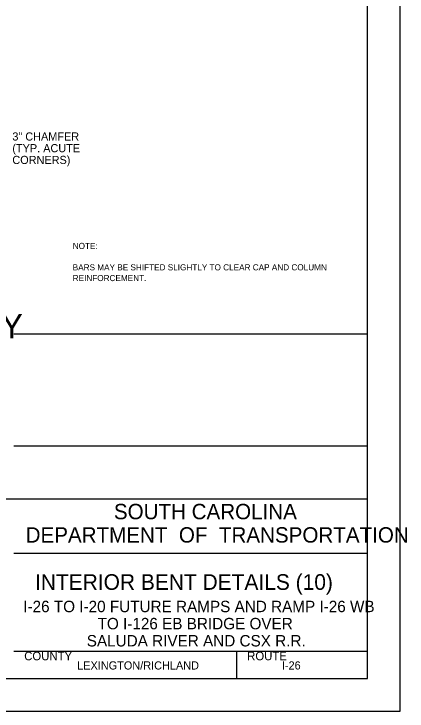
# Model space of a CAD drawing. Extents: x -146.3 to -98.2, y -113.4 to -84.1.
# Drawn here: x -106.2 to -98.17, y -113.39 to -99.15 of the extents above; entities that cross this region are included whole.
import ezdxf

# ---------------------------------------------------------------- set-up
doc = ezdxf.new("R2010")
doc.units = 0
for name, color, linetype in [('BR_AUTO DIMENSION', 7, 'Continuous'), ('BR_BORDER LINES', 7, 'Continuous'), ('BR_TEXT', 7, 'Continuous'), ('Level 31', 7, 'Continuous')]:
    doc.layers.add(name, color=color, linetype=linetype)

msp = doc.modelspace()

# ---------------------------------------------------------------- linework, layer by layer
at = {"layer": 'BR_BORDER LINES'}
for p, q in [((-98.979, -112.725), (-98.979, -84.726)), ((-106.201, -105.69), (-98.979, -105.69)), ((-106.201, -107.976), (-98.979, -107.976)), ((-108.979, -109.058), (-98.979, -109.058)), ((-106.201, -110.169), (-98.978, -110.169)), ((-106.201, -112.169), (-98.979, -112.169)), ((-106.071, -112.169), (-98.979, -112.169)), ((-101.645, -112.725), (-101.645, -112.169)), ((-143.866, -112.725), (-98.979, -112.725))]:
    msp.add_line(p, q, dxfattribs=at)
at = {"layer": 'Level 31'}
msp.add_line((-102.59, -110.756), (-102.59, -110.756), dxfattribs=at)
msp.add_lwpolyline([(-146.31, -113.391), (-98.311, -113.391), (-98.311, -84.059), (-146.31, -84.059)], close=True, dxfattribs=at)

# ---------------------------------------------------------------- texts
at = {"layer": 'BR_AUTO DIMENSION'}
for s, height, p in [('3" CHAMFER', 0.1662, (-106.233, -101.739)), ('(TYP. ACUTE', 0.16625, (-106.233, -101.978)), ('CORNERS)', 0.1662, (-106.233, -102.218)), ('NOTE:', 0.125, (-105, -103.954)), ('BARS MAY BE SHIFTED SLIGHTLY TO CLEAR CAP AND COLUMN', 0.125, (-105, -104.391)), ('REINFORCEMENT.', 0.125, (-105, -104.61))]:
    msp.add_text(s, height=height, dxfattribs=at).set_placement(p)
at = {"layer": 'BR_TEXT'}
msp.add_text('PLAN OF SHEAR KEY', height=0.50006, rotation=0, dxfattribs=at).set_placement((-112.893, -105.782))
for s, height, p in [('SOUTH CAROLINA', 0.31449, (-104.159, -109.474)), ('DEPARTMENT  OF  TRANSPORTATION', 0.31449, (-105.962, -109.951)), ('INTERIOR BENT DETAILS (10)', 0.31999, (-105.771, -110.916)), ('I-26 TO I-20 FUTURE RAMPS AND RAMP I-26 WB', 0.23333, (-106.01, -111.372)), ('TO I-126 EB BRIDGE OVER', 0.23333, (-104.492, -111.722)), ('SALUDA RIVER AND CSX R.R.', 0.23333, (-104.713, -112.072)), ('COUNTY', 0.1733, (-105.991, -112.354)), ('ROUTE', 0.1733, (-101.436, -112.354)), ('LEXINGTON/RICHLAND', 0.16666, (-104.909, -112.543)), ('I-26', 0.1667, (-100.727, -112.543))]:
    msp.add_text(s, height=height, dxfattribs=at).set_placement(p)

doc.saveas('drawing.dxf')
